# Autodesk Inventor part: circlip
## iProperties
Created: 2008-06
Part Number: circlip
Document SubType Name: Modeling
Designer: CADCIM
Density: 1 g/cm^3
Author: CADCIM
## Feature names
1. Extrusion1
2. Fillet1
